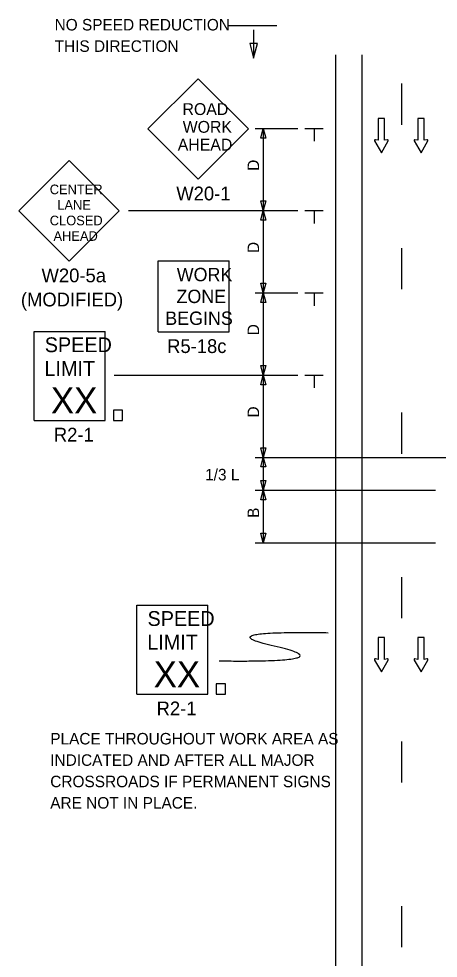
# Model space of a CAD drawing. Extents: x 16733 to 18475, y 5693 to 6915.
# Drawn here: x 16755 to 17010, y 6344 to 6915 of the extents above; entities that cross this region are included whole.
import ezdxf

# ---------------------------------------------------------------- set-up
doc = ezdxf.new("R2010")
doc.units = 0
for name, color, linetype in [('ALI_LEGAL_EX', 7, 'Continuous'), ('MT_SCRATCH_LEVEL_E', 7, 'Continuous'), ('PAVT_EDGE_EX', 7, 'Continuous'), ('TRAFFIC_SIGNS_PR', 7, 'Continuous'), ('TYPICAL_TEXT_DIMEN_PR', 7, 'Continuous')]:
    doc.layers.add(name, color=color, linetype=linetype)

msp = doc.modelspace()

# ---------------------------------------------------------------- linework, layer by layer
at = {"layer": 'ALI_LEGAL_EX'}
for points in [[(16987.43, 6875.6), (16987.43, 6850.6)], [(16987.43, 6775.6), (16987.43, 6750.6)], [(16987.43, 6675.6), (16987.43, 6650.6)], [(16987.43, 6575.6), (16987.43, 6550.6)], [(16987.43, 6475.6), (16987.43, 6450.6)], [(16987.43, 6375.6), (16987.43, 6350.6)]]:
    msp.add_lwpolyline(points, dxfattribs=at)
at = {"layer": 'MT_SCRATCH_LEVEL_E'}
for p, q in [((16977.1, 6854.39), (16973.36, 6854.39)), ((16973.36, 6854.39), (16973.36, 6841.13)), ((16977.1, 6854.39), (16973.36, 6854.39)), ((16973.36, 6854.39), (16973.36, 6841.13)), ((16977.1, 6841.13), (16977.1, 6854.39)), ((16977.1, 6841.13), (16977.1, 6854.39)), ((17001.17, 6854.39), (16997.43, 6854.39)), ((16997.43, 6854.39), (16997.43, 6841.13)), ((17001.17, 6854.39), (16997.43, 6854.39)), ((16997.43, 6854.39), (16997.43, 6841.13)), ((17001.17, 6841.13), (17001.17, 6854.39)), ((17001.17, 6841.13), (17001.17, 6854.39)), ((16971.1, 6840.77), (16975.25, 6833.53)), ((16971.1, 6840.77), (16975.25, 6833.53)), ((16973.36, 6841.13), (16971.58, 6841.45)), ((16973.36, 6841.13), (16971.58, 6841.45)), ((16975.25, 6833.53), (16979.36, 6840.77)), ((16975.25, 6833.53), (16979.36, 6840.77)), ((16978.88, 6841.45), (16977.1, 6841.13)), ((16978.88, 6841.45), (16977.1, 6841.13)), ((16995.18, 6840.77), (16999.32, 6833.53)), ((16995.18, 6840.77), (16999.32, 6833.53)), ((16997.43, 6841.13), (16995.65, 6841.45)), ((16997.43, 6841.13), (16995.65, 6841.45)), ((16999.32, 6833.53), (17003.43, 6840.77)), ((16999.32, 6833.53), (17003.43, 6840.77)), ((17002.95, 6841.45), (17001.17, 6841.13)), ((17002.95, 6841.45), (17001.17, 6841.13)), ((16977.1, 6538.76), (16973.36, 6538.76)), ((16973.36, 6538.76), (16973.36, 6525.51)), ((16977.1, 6538.76), (16973.36, 6538.76)), ((16973.36, 6538.76), (16973.36, 6525.51)), ((16977.1, 6525.51), (16977.1, 6538.76)), ((16977.1, 6525.51), (16977.1, 6538.76)), ((17001.17, 6538.76), (16997.43, 6538.76)), ((16997.43, 6538.76), (16997.43, 6525.51)), ((17001.17, 6538.76), (16997.43, 6538.76)), ((16997.43, 6538.76), (16997.43, 6525.51)), ((17001.17, 6525.51), (17001.17, 6538.76)), ((17001.17, 6525.51), (17001.17, 6538.76)), ((16971.1, 6525.14), (16975.25, 6517.9)), ((16971.1, 6525.14), (16975.25, 6517.9)), ((16973.36, 6525.51), (16971.58, 6525.82)), ((16973.36, 6525.51), (16971.58, 6525.82)), ((16975.25, 6517.9), (16979.36, 6525.14)), ((16975.25, 6517.9), (16979.36, 6525.14)), ((16978.88, 6525.82), (16977.1, 6525.51)), ((16978.88, 6525.82), (16977.1, 6525.51)), ((16995.18, 6525.14), (16999.32, 6517.9)), ((16995.18, 6525.14), (16999.32, 6517.9)), ((16997.43, 6525.51), (16995.65, 6525.82)), ((16997.43, 6525.51), (16995.65, 6525.82)), ((16999.32, 6517.9), (17003.43, 6525.14)), ((16999.32, 6517.9), (17003.43, 6525.14)), ((17002.95, 6525.82), (17001.17, 6525.51)), ((17002.95, 6525.82), (17001.17, 6525.51))]:
    msp.add_line(p, q, dxfattribs=at)
for centre, start, end in [((16971.51, 6840.99), 80.0362, 209.7731), ((16971.51, 6840.99), 80.0362, 209.7731), ((16978.96, 6840.99), 330.4248, 99.9638), ((16978.96, 6840.99), 330.4248, 99.9638), ((16995.59, 6840.99), 80.0362, 209.7731), ((16995.59, 6840.99), 80.0362, 209.7731), ((17003.03, 6840.99), 330.4248, 99.9638), ((17003.03, 6840.99), 330.4248, 99.9638), ((16971.51, 6525.36), 80.0362, 209.7731), ((16971.51, 6525.36), 80.0362, 209.7731), ((16978.96, 6525.36), 330.4248, 99.9638), ((16978.96, 6525.36), 330.4248, 99.9638), ((16995.59, 6525.36), 80.0362, 209.7731), ((16995.59, 6525.36), 80.0362, 209.7731), ((17003.03, 6525.36), 330.4248, 99.9638), ((17003.03, 6525.36), 330.4248, 99.9638)]:
    msp.add_arc(centre, 0.463, start, end, dxfattribs=at)
at = {"layer": 'PAVT_EDGE_EX'}
for p, q in [((16947.43, 6893.09), (16947.43, 6095.81)), ((16963.43, 6893.09), (16963.43, 6095.81))]:
    msp.add_line(p, q, dxfattribs=at)
at = {"layer": 'TRAFFIC_SIGNS_PR'}
for p, q in [((16863.84, 6878.58), (16833.29, 6848.03)), ((16894.39, 6848.03), (16863.84, 6878.58)), ((16833.29, 6848.03), (16863.84, 6817.48)), ((16863.84, 6817.48), (16894.39, 6848.03)), ((16785.32, 6828.78), (16754.77, 6798.23)), ((16815.87, 6798.23), (16785.32, 6828.78)), ((16754.77, 6798.23), (16785.32, 6767.68)), ((16785.32, 6767.68), (16815.87, 6798.23)), ((16839.56, 6724.68), (16839.56, 6767.88)), ((16839.56, 6767.88), (16882.76, 6767.88)), ((16882.76, 6724.68), (16882.76, 6767.88)), ((16764.09, 6724.86), (16807.29, 6724.86)), ((16764.09, 6670.86), (16764.09, 6724.86)), ((16807.29, 6670.86), (16807.29, 6724.86)), ((16839.56, 6724.68), (16882.76, 6724.68)), ((16764.09, 6670.86), (16807.29, 6670.86)), ((16826.56, 6558.41), (16869.76, 6558.41)), ((16826.56, 6504.41), (16826.56, 6558.41)), ((16869.76, 6504.41), (16869.76, 6558.41)), ((16826.56, 6504.41), (16869.76, 6504.41))]:
    msp.add_line(p, q, dxfattribs=at)
for points in [[(16812.3, 6670.86), (16817.9, 6670.86), (16817.9, 6677.03), (16812.3, 6677.03)], [(16874.78, 6504.41), (16880.37, 6504.41), (16880.37, 6510.58), (16874.78, 6510.58)]]:
    msp.add_lwpolyline(points, close=True, dxfattribs=at)
msp.add_open_spline([(16876.64, 6524.62), (16953.27, 6523.72), (16868.24, 6543.07), (16942.79, 6541.77)], degree=2, dxfattribs=at)
at = {"layer": 'TYPICAL_TEXT_DIMEN_PR'}
for p, q in [((16911.71, 6910.79), (16882.27, 6910.79)), ((16897.54, 6908.29), (16897.54, 6891.17)), ((16897.54, 6899.96), (16895.18, 6899.96)), ((16895.18, 6899.96), (16897.54, 6891.17)), ((16897.54, 6891.17), (16899.89, 6899.96)), ((16899.89, 6899.96), (16897.54, 6899.96)), ((16898.43, 6848.38), (16924.43, 6848.38)), ((16901.86, 6842.52), (16903.43, 6848.38)), ((16903.43, 6848.38), (16903.43, 6798.38)), ((16903.43, 6848.38), (16905, 6842.52)), ((16928.68, 6848.38), (16939.93, 6848.38)), ((16934.31, 6848.38), (16934.31, 6840.59)), ((16903.43, 6842.52), (16901.86, 6842.52)), ((16905, 6842.52), (16903.43, 6842.52)), ((16903.43, 6798.38), (16901.86, 6804.24)), ((16901.86, 6804.24), (16903.43, 6804.24)), ((16903.43, 6804.24), (16905, 6804.24)), ((16905, 6804.24), (16903.43, 6798.38)), ((16821.46, 6798.38), (16924.43, 6798.38)), ((16901.86, 6792.52), (16903.43, 6798.38)), ((16903.43, 6798.38), (16905, 6792.52)), ((16903.43, 6798.38), (16903.43, 6748.38)), ((16928.68, 6798.38), (16939.93, 6798.38)), ((16934.31, 6798.38), (16934.31, 6790.59)), ((16903.43, 6792.52), (16901.86, 6792.52)), ((16905, 6792.52), (16903.43, 6792.52)), ((16903.43, 6748.38), (16901.86, 6754.24)), ((16901.86, 6754.24), (16903.43, 6754.24)), ((16903.43, 6754.24), (16905, 6754.24)), ((16905, 6754.24), (16903.43, 6748.38)), ((16898.43, 6748.38), (16924.43, 6748.38)), ((16901.86, 6742.52), (16903.43, 6748.38)), ((16903.43, 6748.38), (16903.43, 6698.38)), ((16903.43, 6748.38), (16905, 6742.52)), ((16928.68, 6748.38), (16939.93, 6748.38)), ((16934.31, 6748.38), (16934.31, 6740.59)), ((16903.43, 6742.52), (16901.86, 6742.52)), ((16905, 6742.52), (16903.43, 6742.52)), ((16903.43, 6698.38), (16901.86, 6704.24)), ((16901.86, 6704.24), (16903.43, 6704.24)), ((16903.43, 6704.24), (16905, 6704.24)), ((16905, 6704.24), (16903.43, 6698.38)), ((16812.71, 6698.38), (16924.43, 6698.38)), ((16901.86, 6692.52), (16903.43, 6698.38)), ((16903.43, 6698.38), (16903.43, 6648.38)), ((16903.43, 6698.38), (16905, 6692.52)), ((16928.68, 6698.38), (16939.93, 6698.38)), ((16934.31, 6698.38), (16934.31, 6690.59)), ((16903.43, 6692.52), (16901.86, 6692.52)), ((16905, 6692.52), (16903.43, 6692.52)), ((16903.43, 6648.38), (16901.86, 6654.24)), ((16901.86, 6654.24), (16903.43, 6654.24)), ((16903.43, 6654.24), (16905, 6654.24)), ((16905, 6654.24), (16903.43, 6648.38)), ((16898.43, 6648.38), (17027.57, 6648.38)), ((16901.86, 6642.52), (16903.43, 6648.38)), ((16903.43, 6648.38), (16903.43, 6628.39)), ((16903.43, 6648.38), (16905, 6642.52)), ((16903.43, 6642.52), (16901.86, 6642.52)), ((16905, 6642.52), (16903.43, 6642.52)), ((16903.43, 6628.39), (16901.86, 6634.25)), ((16901.86, 6634.25), (16903.43, 6634.25)), ((16903.43, 6634.25), (16905, 6634.25)), ((16905, 6634.25), (16903.43, 6628.39)), ((16898.43, 6628.39), (17008.13, 6628.39)), ((16901.86, 6622.53), (16903.43, 6628.39)), ((16903.43, 6628.39), (16903.43, 6596.33)), ((16903.43, 6628.39), (16905, 6622.53)), ((16903.43, 6622.53), (16901.86, 6622.53)), ((16905, 6622.53), (16903.43, 6622.53)), ((16903.43, 6596.33), (16901.86, 6602.19)), ((16901.86, 6602.19), (16903.43, 6602.19)), ((16903.43, 6602.19), (16905, 6602.19)), ((16905, 6602.19), (16903.43, 6596.33)), ((16898.43, 6596.33), (17008.13, 6596.33))]:
    msp.add_line(p, q, dxfattribs=at)

# ---------------------------------------------------------------- texts
at = {"layer": 'TRAFFIC_SIGNS_PR'}
for s, height, p in [('ROAD', 7.2, (16854.33, 6856.51)), ('WORK', 7.2, (16854.45, 6845.71)), ('AHEAD', 7.2, (16851.42, 6834.91)), ('W20-1', 8.37, (16850.53, 6804.61)), ('W20-5a', 8.37, (16768.6, 6754.81)), ('WORK', 8.119, (16850.81, 6755.47)), ('(MODIFIED)', 8.37, (16756.06, 6740.14)), ('ZONE', 8.119, (16850.68, 6742.19)), ('BEGINS', 8.119, (16843.85, 6728.9)), ('SPEED', 9, (16770.57, 6712.33)), ('R5-18c', 8.37, (16844.97, 6711.81)), ('LIMIT', 9, (16770.39, 6697.93)), ('XX', 15.785, (16774.34, 6675.08)), ('R2-1', 8.37, (16776.1, 6657.99)), ('SPEED', 9, (16833.05, 6545.88)), ('LIMIT', 9, (16832.87, 6531.48)), ('XX', 15.785, (16836.81, 6508.63)), ('R2-1', 8.37, (16838.57, 6491.54)), ('PLACE THROUGHOUT WORK AREA AS', 7, (16773.91, 6473.82)), ('INDICATED AND AFTER ALL MAJOR', 7, (16773.91, 6460.82)), ('CROSSROADS IF PERMANENT SIGNS', 7, (16773.91, 6447.82)), ('ARE NOT IN PLACE.', 7, (16773.91, 6434.82))]:
    msp.add_text(s, height=height, dxfattribs=at).set_placement(p)
at = {"layer": 'TYPICAL_TEXT_DIMEN_PR'}
for s, height, p in [('NO SPEED REDUCTION', 7, (16776.55, 6907.91)), ('THIS DIRECTION', 7, (16776.55, 6894.91)), ('CENTER', 5.85, (16773.6, 6808.36)), ('LANE', 5.85, (16778.18, 6798.91)), ('CLOSED', 5.85, (16773.6, 6789.46)), ('AHEAD', 5.85, (16775.88, 6780.01)), ('1/3 L', 7, (16868.07, 6634.38))]:
    msp.add_text(s, height=height, dxfattribs=at).set_placement(p)
for s, p in [('D', (16900.88, 6822.6)), ('D', (16900.88, 6772.6)), ('D', (16900.88, 6722.6)), ('D', (16900.88, 6672.6)), ('B', (16900.88, 6611.59))]:
    msp.add_text(s, height=7, rotation=90, dxfattribs=at).set_placement(p)

doc.saveas('drawing.dxf')
